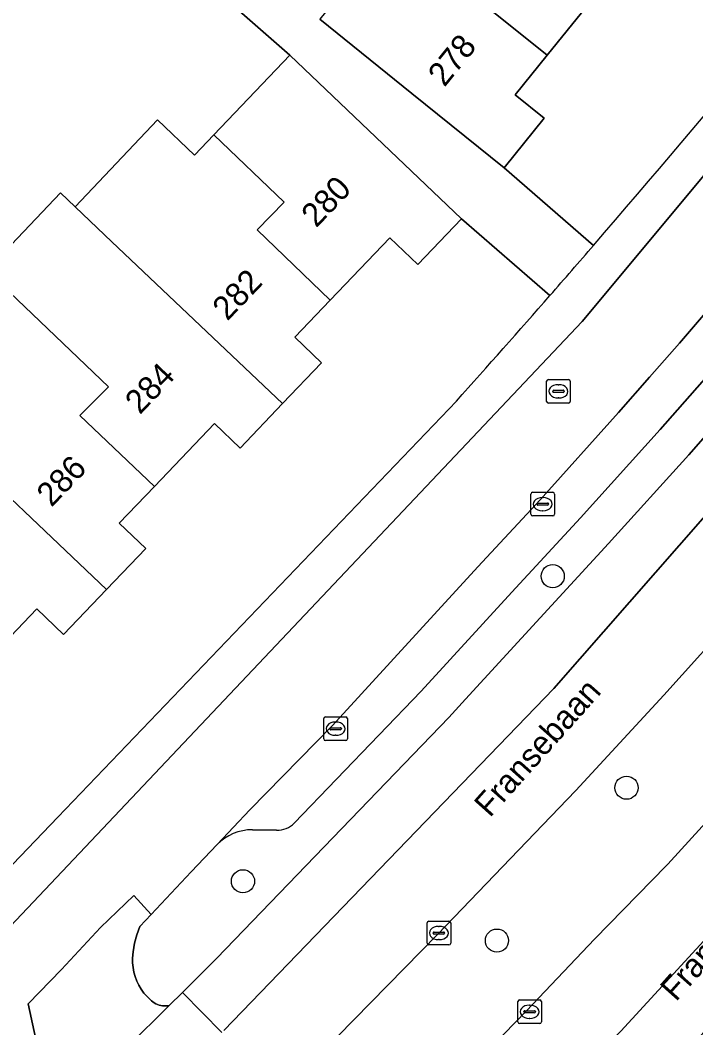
# Model space of a CAD drawing. Extents: x 158472 to 159562, y 388525 to 389606.
# Drawn here: x 158642.99 to 158671.54, y 388856.57 to 388899.14 of the extents above; entities that cross this region are included whole.
import ezdxf

# ---------------------------------------------------------------- set-up
doc = ezdxf.new("R2010")
doc.units = 0
for name, color, linetype in [('IMGEO_Berm_groen', 7, 'Continuous'), ('IMGEO_Boom', 7, 'Continuous'), ('IMGEO_Erf', 7, 'Continuous'), ('IMGEO_Kolk', 7, 'Continuous'), ('IMGEO_Openbare_ruimte_label', 7, 'Continuous'), ('IMGEO_Pand', 7, 'Continuous'), ('IMGEO_Pand_nummerreeks', 7, 'Continuous'), ('IMGEO_Parkeervlak_open', 7, 'Continuous'), ('IMGEO_Rijbaan_lokaal_gesloten', 7, 'Continuous'), ('IMGEO_Rijbaan_lokaal_open', 7, 'Continuous'), ('IMGEO_Rioolput', 7, 'Continuous'), ('IMGEO_Voetpad_open', 7, 'Continuous')]:
    doc.layers.add(name, color=color, linetype=linetype)

msp = doc.modelspace()

# ---------------------------------------------------------------- linework, layer by layer
at = {"layer": 'IMGEO_Berm_groen'}
for points in [[(158671.24, 388880.784), (158673.533, 388883.403), (158676.576, 388886.911), (158679.398, 388890.243), (158682.394, 388893.941), (158685.595, 388897.967), (158688.786, 388901.962), (158687.514, 388902.953), (158684.205, 388898.809), (158681.137, 388894.95), (158678.157, 388891.271), (158675.353, 388887.96), (158672.318, 388884.462), (158670.036, 388881.855), (158666.663, 388878.125), (158663.767, 388874.978), (158659.928, 388870.792), (158654.57, 388865.224)], [(158689.146, 388892.868), (158685.824, 388888.819), (158680.221, 388882.024), (158677.431, 388878.763), (158673.414, 388874.206), (158670.19, 388870.631), (158666.464, 388866.603), (158666.105, 388866.215), (158660.635, 388860.529), (158656.398, 388856.202), (158654.172, 388854.084)], [(158651.312, 388864.316), (158650.223, 388863.164), (158648.531, 388861.366), (158648.047, 388860.846), (158647.922, 388860.502), (158647.829, 388860.149), (158647.768, 388859.788), (158647.743, 388859.515), (158647.744, 388859.317), (158647.762, 388859.119), (158647.798, 388858.924), (158647.851, 388858.733), (158647.921, 388858.547), (158648.007, 388858.368), (158648.109, 388858.198), (158648.225, 388858.037), (158648.356, 388857.888), (158648.499, 388857.751), (158648.539, 388857.717), (158648.597, 388857.668), (158648.659, 388857.625), (158648.725, 388857.588), (158648.794, 388857.557), (158648.865, 388857.531), (158648.938, 388857.513), (158649.013, 388857.501), (158649.088, 388857.495), (158649.164, 388857.497), (158649.239, 388857.505), (158649.292, 388857.515), (158649.845, 388858.063), (158651.306, 388859.511), (158661.102, 388869.689), (158661.805, 388870.456), (158664.954, 388873.888), (158667.853, 388877.039), (158671.24, 388880.784)], [(158653.743, 388846.575), (158659.8, 388852.588), (158661.495, 388854.32), (158664.378, 388857.295), (158667.252, 388860.316), (158670.301, 388863.43), (158670.348, 388863.48), (158672.68, 388866.029), (158675.923, 388869.515), (158679.017, 388873.024)], [(158653.827, 388864.918), (158652.811, 388864.941)]]:
    msp.add_lwpolyline(points, dxfattribs=at)
for centre, radius, start, end in [((158653.851, 388865.915), 0.997, 268.6297, 316.1383), ((158652.813, 388862.825), 2.116, 90.0637, 135.2032)]:
    msp.add_arc(centre, radius, start, end, dxfattribs=at)
at = {"layer": 'IMGEO_Boom'}
for centre in [(158665.49, 388875.653), (158668.608, 388866.715), (158652.407, 388862.762), (158663.133, 388860.257)]:
    msp.add_circle(centre, 0.489, dxfattribs=at)
at = {"layer": 'IMGEO_Erf'}
for points in [[(158681.727, 388907.247), (158688.881, 388916.431), (158683.73, 388920.567), (158681.495, 388917.794), (158682.74, 388916.779), (158679.952, 388913.298), (158678.687, 388914.31), (158677.464, 388912.792), (158678.711, 388911.788), (158677.223, 388909.942), (158675.571, 388907.892), (158674.328, 388908.894), (158672.051, 388906.068), (158670.706, 388904.398), (158671.908, 388903.429), (158670.402, 388901.56), (158668.766, 388899.53), (158667.556, 388900.505), (158665.263, 388897.66), (158663.911, 388895.983), (158665.126, 388895.004), (158663.438, 388892.908), (158667.216, 388889.629)], [(158641.567, 388888.565), (158644.692, 388891.853), (158645.314, 388891.262), (158648.801, 388894.93), (158650.361, 388893.447), (158651.174, 388894.299), (158654.39, 388897.669), (158646.076, 388904.95), (158640.8, 388899.447)], [(158665.374, 388887.512), (158661.636, 388890.756), (158659.787, 388888.819), (158658.605, 388889.947), (158656.094, 388887.315), (158654.599, 388885.748), (158655.727, 388884.672), (158654.082, 388882.949), (158652.286, 388881.066), (158651.199, 388882.103), (158648.663, 388879.445), (158647.18, 388877.89), (158648.296, 388876.825), (158646.641, 388875.09), (158644.829, 388873.191), (158643.694, 388874.274), (158641.182, 388871.642)], [(158641.079, 388861.821), (158644.581, 388865.476), (158661.42, 388883.05)]]:
    msp.add_lwpolyline(points, dxfattribs=at)
for centre, radius, start, end in [((158308.503, 389199.866), 474.259, 319.14468, 321.90242), ((158316.591, 389192.603), 463.389, 318.08567, 318.82283)]:
    msp.add_arc(centre, radius, start, end, dxfattribs=at)
at = {"layer": 'IMGEO_Kolk'}
for p, q in [((158664.568, 388878.271), (158664.568, 388879.123)), ((158664.643, 388879.197), (158665.495, 388879.197)), ((158665.569, 388879.123), (158665.569, 388878.271)), ((158664.827, 388878.691), (158664.827, 388878.703)), ((158664.87, 388878.74), (158665.268, 388878.74)), ((158665.056, 388878.977), (158665.081, 388878.977)), ((158665.311, 388878.703), (158665.311, 388878.691)), ((158665.265, 388878.654), (158664.867, 388878.654)), ((158665.079, 388878.417), (158665.054, 388878.417)), ((158665.495, 388878.197), (158664.643, 388878.197)), ((158655.819, 388868.783), (158655.819, 388869.635)), ((158655.894, 388869.709), (158656.746, 388869.709)), ((158656.307, 388869.489), (158656.332, 388869.489)), ((158656.82, 388869.635), (158656.82, 388868.783)), ((158656.078, 388869.203), (158656.078, 388869.215)), ((158656.516, 388869.166), (158656.118, 388869.166)), ((158656.121, 388869.252), (158656.519, 388869.252)), ((158656.33, 388868.929), (158656.305, 388868.929)), ((158656.562, 388869.215), (158656.562, 388869.203)), ((158656.746, 388868.709), (158655.894, 388868.709)), ((158660.181, 388860.15), (158660.181, 388861.002)), ((158660.256, 388861.076), (158661.108, 388861.076)), ((158660.669, 388860.856), (158660.694, 388860.856)), ((158661.182, 388861.002), (158661.182, 388860.15)), ((158660.44, 388860.57), (158660.44, 388860.582)), ((158660.878, 388860.533), (158660.48, 388860.533)), ((158660.483, 388860.619), (158660.881, 388860.619)), ((158660.924, 388860.582), (158660.924, 388860.57)), ((158661.108, 388860.076), (158660.256, 388860.076)), ((158660.692, 388860.296), (158660.667, 388860.296)), ((158664.016, 388856.825), (158664.016, 388857.677)), ((158664.091, 388857.751), (158664.943, 388857.751)), ((158664.504, 388857.531), (158664.529, 388857.531)), ((158665.017, 388857.677), (158665.017, 388856.825)), ((158664.275, 388857.245), (158664.275, 388857.257)), ((158664.713, 388857.208), (158664.315, 388857.208)), ((158664.318, 388857.294), (158664.716, 388857.294)), ((158664.527, 388856.971), (158664.502, 388856.971)), ((158664.759, 388857.257), (158664.759, 388857.245)), ((158664.943, 388856.751), (158664.091, 388856.751))]:
    msp.add_line(p, q, dxfattribs=at)
for points in [[(158664.568, 388878.271), (158664.568, 388879.123)], [(158664.643, 388879.197), (158665.495, 388879.197)], [(158665.569, 388879.123), (158665.569, 388878.271)], [(158665.495, 388878.197), (158664.643, 388878.197)], [(158655.819, 388868.783), (158655.819, 388869.635)], [(158655.894, 388869.709), (158656.746, 388869.709)], [(158656.82, 388869.635), (158656.82, 388868.783)], [(158656.746, 388868.709), (158655.894, 388868.709)], [(158660.181, 388860.15), (158660.181, 388861.002)], [(158660.256, 388861.076), (158661.108, 388861.076)], [(158661.182, 388861.002), (158661.182, 388860.15)], [(158661.108, 388860.076), (158660.256, 388860.076)], [(158664.016, 388856.825), (158664.016, 388857.677)], [(158664.091, 388857.751), (158664.943, 388857.751)], [(158665.017, 388857.677), (158665.017, 388856.825)], [(158664.943, 388856.751), (158664.091, 388856.751)]]:
    msp.add_lwpolyline(points, dxfattribs=at)
for centre, radius, start, end in [((158664.645, 388879.121), 0.0765, 91.552, 178.448), ((158664.645, 388879.121), 0.0765, 91.552, 178.448), ((158665.493, 388879.121), 0.0765, 1.552, 88.448), ((158665.493, 388879.121), 0.0765, 1.552, 88.448), ((158664.867, 388878.7), 0.0403, 85.8775, 175.7526), ((158664.864, 388878.69), 0.0366, 178.938, 274.7102), ((158665.268, 388878.697), 0.043, 264.8664, 352.4533), ((158665.272, 388878.702), 0.0386, 1.7309, 96.639), ((158664.645, 388878.273), 0.0765, 181.552, 268.448), ((158664.645, 388878.273), 0.0765, 181.552, 268.448), ((158665.493, 388878.273), 0.0765, 271.552, 358.448), ((158665.493, 388878.273), 0.0765, 271.552, 358.448), ((158655.896, 388869.633), 0.0765, 91.552, 178.448), ((158655.896, 388869.633), 0.0765, 91.552, 178.448), ((158656.744, 388869.633), 0.0765, 1.552, 88.448), ((158656.744, 388869.633), 0.0765, 1.552, 88.448), ((158656.118, 388869.212), 0.0403, 85.8775, 175.7526), ((158656.115, 388869.202), 0.0366, 178.938, 274.7102), ((158656.519, 388869.209), 0.043, 264.8664, 352.4533), ((158656.523, 388869.214), 0.0386, 1.7309, 96.639), ((158655.896, 388868.785), 0.0765, 181.552, 268.448), ((158655.896, 388868.785), 0.0765, 181.552, 268.448), ((158656.744, 388868.785), 0.0765, 271.552, 358.448), ((158656.744, 388868.785), 0.0765, 271.552, 358.448), ((158660.258, 388861), 0.0765, 91.552, 178.448), ((158660.258, 388861), 0.0765, 91.552, 178.448), ((158661.106, 388861), 0.0765, 1.552, 88.448), ((158661.106, 388861), 0.0765, 1.552, 88.448), ((158660.48, 388860.579), 0.0403, 85.8775, 175.7526), ((158660.477, 388860.569), 0.0366, 178.938, 274.7102), ((158660.881, 388860.576), 0.043, 264.8664, 352.4533), ((158660.885, 388860.581), 0.0386, 1.7309, 96.639), ((158660.258, 388860.152), 0.0765, 181.552, 268.448), ((158660.258, 388860.152), 0.0765, 181.552, 268.448), ((158661.106, 388860.152), 0.0765, 271.552, 358.448), ((158661.106, 388860.152), 0.0765, 271.552, 358.448), ((158664.093, 388857.675), 0.0765, 91.552, 178.448), ((158664.093, 388857.675), 0.0765, 91.552, 178.448), ((158664.941, 388857.675), 0.0765, 1.552, 88.448), ((158664.941, 388857.675), 0.0765, 1.552, 88.448), ((158664.315, 388857.254), 0.0403, 85.8775, 175.7526), ((158664.312, 388857.244), 0.0366, 178.938, 274.7102), ((158664.716, 388857.251), 0.043, 264.8664, 352.4533), ((158664.72, 388857.256), 0.0386, 1.7309, 96.639), ((158664.093, 388856.827), 0.0765, 181.552, 268.448), ((158664.093, 388856.827), 0.0765, 181.552, 268.448), ((158664.941, 388856.827), 0.0765, 271.552, 358.448), ((158664.941, 388856.827), 0.0765, 271.552, 358.448)]:
    msp.add_arc(centre, radius, start, end, dxfattribs=at)
for centre, major_axis, ratio, start_param, end_param in [((158665.055, 388878.697), (-0.387, 0.002), 0.722429, 4.712389, 7.853982), ((158665.08, 388878.697), (-0.39, 0.002), 0.717154, 1.570796, 4.712389), ((158656.306, 388869.209), (-0.387, 0.002), 0.722429, 4.712389, 7.853982), ((158656.331, 388869.209), (-0.39, 0.002), 0.717154, 1.570796, 4.712389), ((158660.668, 388860.576), (-0.387, 0.002), 0.722429, 4.712389, 7.853982), ((158660.693, 388860.576), (-0.39, 0.002), 0.717154, 1.570796, 4.712389), ((158664.503, 388857.251), (-0.387, 0.002), 0.722429, 4.712389, 7.853982), ((158664.528, 388857.251), (-0.39, 0.002), 0.717154, 1.570796, 4.712389)]:
    msp.add_ellipse(centre, major_axis=major_axis, ratio=ratio, start_param=start_param, end_param=end_param, dxfattribs=at)
at = {"layer": 'IMGEO_Pand'}
for points in [[(158659.741, 388904.253), (158662.99, 388901.63), (158661.93, 388900.34), (158665.263, 388897.66), (158667.556, 388900.505), (158668.766, 388899.53), (158670.402, 388901.56), (158662.596, 388907.797)], [(158659.741, 388904.253), (158655.653, 388899.181), (158659.544, 388896.045), (158663.438, 388892.908), (158665.126, 388895.004), (158663.911, 388895.983), (158665.263, 388897.66), (158661.93, 388900.34), (158662.99, 388901.63)], [(158656.094, 388887.315), (158658.605, 388889.947), (158659.787, 388888.819), (158661.636, 388890.756), (158658.018, 388894.207), (158654.39, 388897.669), (158651.174, 388894.299), (158654.15, 388891.46), (158653, 388890.28)], [(158656.094, 388887.315), (158653, 388890.28), (158654.15, 388891.46), (158651.174, 388894.299), (158650.361, 388893.447), (158648.801, 388894.93), (158645.314, 388891.262), (158646.868, 388889.785), (158654.082, 388882.949), (158655.727, 388884.672), (158654.599, 388885.748)], [(158648.663, 388879.445), (158651.199, 388882.103), (158652.286, 388881.066), (158654.082, 388882.949), (158646.868, 388889.785), (158645.314, 388891.262), (158644.692, 388891.853), (158641.567, 388888.565), (158646.72, 388883.65), (158645.52, 388882.44)], [(158641.567, 388888.565), (158637.246, 388884.018), (158639.407, 388881.965), (158646.641, 388875.09), (158648.296, 388876.825), (158647.18, 388877.89), (158648.663, 388879.445), (158645.52, 388882.44), (158646.72, 388883.65)], [(158639.407, 388881.965), (158637.246, 388884.018), (158633.53, 388880.124), (158635.686, 388878.066), (158636.282, 388878.69), (158639.28, 388875.83), (158638.07, 388874.61), (158641.182, 388871.642), (158643.694, 388874.274), (158644.829, 388873.191), (158646.641, 388875.09)]]:
    msp.add_lwpolyline(points, close=True, dxfattribs=at)
at = {"layer": 'IMGEO_Parkeervlak_open'}
for points in [[(158692.351, 388912.123), (158690.206, 388909.388), (158688.674, 388907.305), (158685.077, 388902.753), (158681.013, 388897.669), (158677.905, 388893.842), (158675.428, 388890.945), (158673.224, 388888.265), (158670.851, 388885.497), (158669.583, 388884.063), (158668.264, 388882.572), (158664.958, 388878.876), (158662.323, 388876.052), (158659.859, 388873.355), (158656.189, 388869.344), (158652.696, 388865.781), (158651.312, 388864.316)], [(158654.57, 388865.224), (158659.928, 388870.792), (158663.767, 388874.978), (158666.663, 388878.125), (158670.036, 388881.855), (158672.318, 388884.462), (158675.353, 388887.96), (158678.157, 388891.271), (158681.137, 388894.95), (158684.205, 388898.809), (158687.514, 388902.953), (158688.832, 388904.601), (158689.345, 388905.243), (158690.825, 388907.265), (158692.161, 388908.96)], [(158652.811, 388864.941), (158653.827, 388864.918)]]:
    msp.add_lwpolyline(points, dxfattribs=at)
for centre, radius, start, end in [((158653.851, 388865.915), 0.997, 268.6297, 316.1383), ((158652.813, 388862.825), 2.116, 90.0637, 135.2032)]:
    msp.add_arc(centre, radius, start, end, dxfattribs=at)
at = {"layer": 'IMGEO_Rijbaan_lokaal_gesloten'}
for points in [[(158816.807, 389052.991), (158817.551, 389053.252), (158816.351, 389056.585), (158812.361, 389054.997), (158810.132, 389053.866), (158806.876, 389051.639), (158804.716, 389049.617), (158803.379, 389048.28), (158800.43, 389044.703), (158777.642, 389014.753), (158751.605, 388980.623), (158732.013, 388954.68), (158705.771, 388920.107), (158682.617, 388890.402), (158665.532, 388870.907), (158651.596, 388856.454)], [(158651.596, 388856.454), (158665.532, 388870.907), (158682.617, 388890.402), (158705.771, 388920.107), (158732.013, 388954.68), (158751.605, 388980.623), (158777.642, 389014.753), (158800.43, 389044.703), (158803.379, 389048.28), (158804.716, 389049.617), (158806.876, 389051.639), (158810.132, 389053.866)], [(158642.3, 388830.16), (158642.462, 388830.323), (158644.297, 388828.539), (158644.976, 388829.209), (158654.546, 388838.744), (158652.694, 388840.633), (158668.364, 388856.424), (158683.318, 388872.712), (158697.002, 388889.186), (158717.328, 388915.448), (158737.178, 388941.567), (158754.114, 388963.852), (158766.121, 388979.65), (158778.301, 388995.677), (158798.192, 389021.851), (158809.433, 389036.528), (158811.777, 389039.288), (158814.069, 389041.449), (158818.297, 389044.22), (158821.97, 389045.718), (158820.551, 389048.928)], [(158822.868, 389043.49), (158821.97, 389045.718), (158818.297, 389044.22), (158814.069, 389041.449), (158811.777, 389039.288), (158809.433, 389036.528), (158798.192, 389021.851), (158778.301, 388995.677), (158766.121, 388979.65), (158754.114, 388963.852), (158737.178, 388941.567), (158717.328, 388915.448), (158697.002, 388889.186), (158683.318, 388872.712), (158668.364, 388856.424), (158652.694, 388840.633), (158654.546, 388838.744), (158654.775, 388838.972), (158671.833, 388856.333), (158672.448, 388857.038), (158674.867, 388859.654), (158677.905, 388862.94)], [(158703.716, 388921.486), (158702.237, 388919.541), (158701.594, 388918.629), (158696.184, 388911.487), (158692.861, 388907.179), (158690.614, 388904.25), (158690.101, 388903.608), (158688.786, 388901.962), (158685.595, 388897.967), (158682.394, 388893.941), (158679.398, 388890.243), (158676.576, 388886.911), (158673.533, 388883.403), (158671.24, 388880.784), (158667.853, 388877.039), (158664.954, 388873.888), (158661.805, 388870.456), (158661.102, 388869.689), (158651.306, 388859.511), (158649.845, 388858.063), (158651.514, 388856.372)], [(158709.718, 388911.287), (158700.675, 388899.419), (158698.796, 388896.983), (158697.521, 388895.303), (158694.933, 388891.894), (158692.302, 388888.672), (158689.133, 388884.755), (158686.992, 388882.254), (158684.423, 388879.16), (158681.461, 388875.79), (158679.017, 388873.024), (158675.923, 388869.515), (158672.68, 388866.029), (158670.348, 388863.48), (158670.301, 388863.43), (158667.252, 388860.316), (158664.378, 388857.295), (158661.495, 388854.32)], [(158637.572, 388837.329), (158638.778, 388838.555), (158643.287, 388843.123), (158654.172, 388854.084), (158656.398, 388856.202), (158660.635, 388860.529), (158666.105, 388866.215), (158666.464, 388866.603), (158670.19, 388870.631), (158673.414, 388874.206), (158677.431, 388878.763), (158680.221, 388882.024), (158685.824, 388888.819), (158689.146, 388892.868)], [(158651.514, 388856.372), (158649.845, 388858.063), (158649.292, 388857.515), (158647.531, 388855.77)]]:
    msp.add_lwpolyline(points, dxfattribs=at)
at = {"layer": 'IMGEO_Rijbaan_lokaal_open'}
for points in [[(158680.692, 388903.184), (158673.719, 388894.796), (158666.738, 388886.416), (158640.359, 388858.532), (158641.243, 388854.184)], [(158643.949, 388854.728), (158643.326, 388857.585), (158644.743, 388859.037), (158646.385, 388860.814), (158647.802, 388862.166), (158648.531, 388861.366), (158650.223, 388863.164), (158651.312, 388864.316), (158652.696, 388865.781), (158656.189, 388869.344), (158659.859, 388873.355), (158662.323, 388876.052), (158664.958, 388878.876), (158668.264, 388882.572), (158669.583, 388884.063), (158670.851, 388885.497), (158673.224, 388888.265), (158675.428, 388890.945), (158677.905, 388893.842), (158681.013, 388897.669), (158685.077, 388902.753)]]:
    msp.add_lwpolyline(points, dxfattribs=at)
at = {"layer": 'IMGEO_Rioolput'}
for p, q in [((158665.231, 388883.037), (158665.231, 388883.889)), ((158665.306, 388883.963), (158666.158, 388883.963)), ((158666.232, 388883.889), (158666.232, 388883.037)), ((158665.49, 388883.457), (158665.49, 388883.469)), ((158665.928, 388883.42), (158665.53, 388883.42)), ((158665.533, 388883.506), (158665.931, 388883.506)), ((158665.719, 388883.743), (158665.744, 388883.743)), ((158665.974, 388883.469), (158665.974, 388883.457)), ((158666.158, 388882.963), (158665.306, 388882.963)), ((158665.742, 388883.183), (158665.717, 388883.183))]:
    msp.add_line(p, q, dxfattribs=at)
for points in [[(158665.231, 388883.037), (158665.231, 388883.889)], [(158665.306, 388883.963), (158666.158, 388883.963)], [(158666.232, 388883.889), (158666.232, 388883.037)], [(158666.158, 388882.963), (158665.306, 388882.963)]]:
    msp.add_lwpolyline(points, dxfattribs=at)
for centre, radius, start, end in [((158665.308, 388883.887), 0.0765, 91.552, 178.448), ((158665.308, 388883.887), 0.0765, 91.552, 178.448), ((158666.156, 388883.887), 0.0765, 1.552, 88.448), ((158666.156, 388883.887), 0.0765, 1.552, 88.448), ((158665.53, 388883.466), 0.0403, 85.8775, 175.7526), ((158665.527, 388883.456), 0.0366, 178.938, 274.7102), ((158665.931, 388883.463), 0.043, 264.8664, 352.4533), ((158665.935, 388883.468), 0.0386, 1.7309, 96.639), ((158665.308, 388883.039), 0.0765, 181.552, 268.448), ((158665.308, 388883.039), 0.0765, 181.552, 268.448), ((158666.156, 388883.039), 0.0765, 271.552, 358.448), ((158666.156, 388883.039), 0.0765, 271.552, 358.448)]:
    msp.add_arc(centre, radius, start, end, dxfattribs=at)
for centre, major_axis, ratio, start_param, end_param in [((158665.718, 388883.463), (-0.387, 0.002), 0.722429, 4.712389, 7.853982), ((158665.743, 388883.463), (-0.39, 0.002), 0.717154, 1.570796, 4.712389)]:
    msp.add_ellipse(centre, major_axis=major_axis, ratio=ratio, start_param=start_param, end_param=end_param, dxfattribs=at)
at = {"layer": 'IMGEO_Voetpad_open'}
for points in [[(158640.8, 388899.447), (158646.076, 388904.95), (158654.39, 388897.669), (158658.018, 388894.207), (158661.636, 388890.756), (158665.374, 388887.512)], [(158661.42, 388883.05), (158644.581, 388865.476), (158641.079, 388861.821), (158636.245, 388856.776), (158634.88, 388855.474), (158638.186, 388852.471), (158641.243, 388854.184), (158640.359, 388858.532), (158666.738, 388886.416), (158673.719, 388894.796), (158680.692, 388903.184)], [(158667.216, 388889.629), (158663.438, 388892.908), (158659.544, 388896.045), (158655.653, 388899.181)], [(158647.531, 388855.77), (158649.292, 388857.515), (158649.239, 388857.505), (158649.164, 388857.497), (158649.088, 388857.495), (158649.013, 388857.501), (158648.938, 388857.513), (158648.865, 388857.531), (158648.794, 388857.557), (158648.725, 388857.588), (158648.659, 388857.625), (158648.597, 388857.668), (158648.539, 388857.717), (158648.499, 388857.751), (158648.356, 388857.888), (158648.225, 388858.037), (158648.109, 388858.198), (158648.007, 388858.368), (158647.921, 388858.547), (158647.851, 388858.733), (158647.798, 388858.924), (158647.762, 388859.119), (158647.744, 388859.317), (158647.743, 388859.515), (158647.768, 388859.788), (158647.829, 388860.149), (158647.922, 388860.502), (158648.047, 388860.846), (158648.531, 388861.366), (158647.802, 388862.166), (158646.385, 388860.814), (158644.743, 388859.037), (158643.326, 388857.585), (158643.949, 388854.728)]]:
    msp.add_lwpolyline(points, dxfattribs=at)
for centre, radius, start, end in [((158308.503, 389199.866), 474.259, 319.14468, 321.90242), ((158368.478, 389147.701), 394.772, 318.76986, 319.17714), ((158368.478, 389147.701), 394.772, 318.76986, 319.17714), ((158316.591, 389192.603), 463.389, 318.08567, 318.82283)]:
    msp.add_arc(centre, radius, start, end, dxfattribs=at)

# ---------------------------------------------------------------- texts
at = {"layer": 'IMGEO_Openbare_ruimte_label'}
for rotation, p in [(48.2428, (158662.835, 388865.423)), (48.3236, (158670.695, 388857.647))]:
    msp.add_text('Fransebaan', height=1, rotation=rotation, dxfattribs=at).set_placement(p)
at = {"layer": 'IMGEO_Pand_nummerreeks'}
for s, rotation, p in [('278', 51.1291, (158660.918, 388896.285)), ('280', 46.3475, (158655.501, 388890.343)), ('282', 46.3475, (158651.746, 388886.408)), ('284', 46.35, (158648.053, 388882.455)), ('286', 46.35, (158644.319, 388878.541))]:
    msp.add_text(s, height=1, rotation=rotation, dxfattribs=at).set_placement(p)

doc.saveas('drawing.dxf')
